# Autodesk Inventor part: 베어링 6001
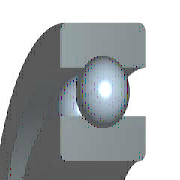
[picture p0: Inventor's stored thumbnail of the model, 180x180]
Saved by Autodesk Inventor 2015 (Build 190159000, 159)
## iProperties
IsCustomPart: 0
Created: 2015-10
Part Number: 베어링 6001
Material: 강, 연강
Description: 깊은 그루브 볼 베어링
Document SubType Name: Modeling
Standard: KS B 2023
Designer: mdu
Standards Organization: KS
Language: ko-KR
Size Designation: 6001 - 12 x 28 x 8
Categories: <MemberInstance><Categories><Category DisplayName="샤프트 부품" InternalName="7f7aeb1f-a693-4053-b835-cee3144e0d98" Mnemonic="SHFT"><Category DisplayName="베어링" Inter
Density: 1 g/cm^3
Appearance: 강철
Author: mdu
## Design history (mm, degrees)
sketch "스케치" dims "d0" = 4.16 (= -0.26 x WD + 0.26 x BD)
  geometry: L1 (1.92, 10)-(6.08, 10); L2 (4, 10)-(4, 7.92); L3 (4, 10)-(4, 12.08); L4 (2.454, 8.608)-(0, 8.608); L5 (0, 6)-(8, 6); L6 (2.454, 11.392)-(0, 11.392); L7 (0, 14)-(8, 14); L8 (8, 6)-(8, 8.608); L9 (5.546, 8.608)-(8, 8.608); L10 (5.546, 11.392)-(8, 11.392); L11 (8, 14)-(8, 11.392); L12 (-1.4, 0)-(8.4, 0) reference; L13 (0, -0.3)-(0, 5.3) reference
  constraints: 22 end point, 4 point on line, 2 collinear, 2 perpendicular, 2 symmetric about line, 1 midpoint, 1 parallel, 14 other
  dimensions: "d9" = 12 diameter of L5 L12 (= WD); "d11" = 28 diameter of L7 L12 (= BD); "d12" = 8 distance between parallel lines of L8 L13 (= KB); "d13" = 17.216 diameter of L9 L12 (= 0.326 x BD + 0.674 x WD)
revolve "본체" stored, may be unused: angle "d6" = 90 deg
revolve "볼" stored, may be unused: angle "d7" = 90 deg
pattern_circular "IDS_ARRAYBALL[SIMPL:T]" dims angle "d3" = 360 deg
body "Solid1"
fillet "모깎기1" dims "d1" = 0.3 (= KRS)
other parameters: "WD" = 12 [user parameter; used in 5 equation terms], "BD" = 28 [user parameter; used in 5 equation terms], "KB" = 8 [user parameter; used in 1 equation term], "KRS" = 0.3 [user parameter; used in 1 equation term], "d4" = 0, "d5" = 0, "d8" = 0, "d14" = 0, "d15" = 0, "BBA" = 0 [user parameter], "BC0" = 2360000 [user parameter], "BC" = 5070000 [user parameter], "BR" = 14 (= 0.5 x BD) [user parameter], "WR" = 6 (= 0.5 x WD) [user parameter]
